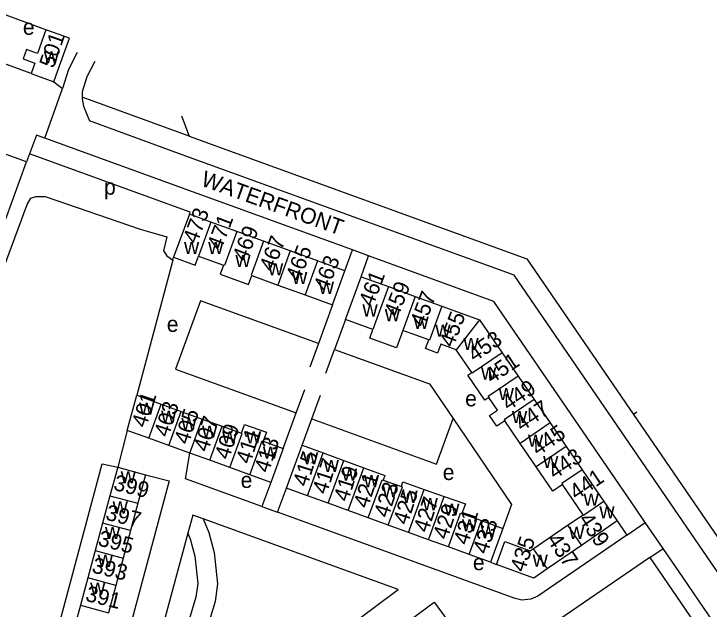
# Model space of a CAD drawing. Extents: x 154320 to 156262, y 382651 to 384180.
# Drawn here: x 155831.3 to 156007.7, y 383414.4 to 383565.5 of the extents above; entities that cross this region are included whole.
import ezdxf

# ---------------------------------------------------------------- set-up
doc = ezdxf.new("R2010")
doc.units = 0
for name, color, linetype in [('BLT_Basislijn', 7, 'Continuous'), ('BLT_Bebouwing', 7, 'Continuous'), ('BLT_Centroide', 7, 'Continuous'), ('BLT_Huisnummer', 7, 'Continuous'), ('BLT_Huisnummer_ tussenligend', 7, 'Continuous'), ('BLT_Onderverdeling_panden', 7, 'Continuous'), ('BLT_Straatnaam', 7, 'Continuous'), ('BLT_Vlakafsluiter', 7, 'Continuous')]:
    doc.layers.add(name, color=color, linetype=linetype)

msp = doc.modelspace()

# ---------------------------------------------------------------- linework, layer by layer
at = {"layer": 'BLT_Basislijn'}
for p, q in [((155839.44, 383561.42), (155828.37, 383565.46)), ((155835.65, 383550.35), (155824.35, 383554.45)), ((155847.33, 383555.63), (155845.19, 383551.33)), ((155851.81, 383553.41), (155849.84, 383549.45)), ((155845.19, 383551.33), (155843.65, 383546.5)), ((155841.45, 383548.21), (155843.65, 383546.5)), ((155875.74, 383534.42), (155848.6, 383544.29)), ((155835.3, 383529.97), (155834.5, 383527.86)), ((155876.04, 383515.15), (155835.3, 383529.97)), ((155875.83, 383514.59), (155876.04, 383515.15)), ((155915.27, 383500.24), (155917.18, 383505.52)), ((155871.64, 383502.96), (155871.84, 383503.71)), ((155919.39, 383498.74), (155921.3, 383504.02)), ((155871.64, 383502.96), (155862.48, 383468.66)), ((155912.14, 383491.6), (155908.57, 383481.75)), ((155915.42, 383487.85), (155912.67, 383480.28)), ((155908.57, 383481.75), (155906.4, 383475.76)), ((155902.91, 383464.14), (155905.09, 383470.09)), ((155906.89, 383462.69), (155909.06, 383468.64)), ((155899.62, 383455.13), (155902.91, 383464.14)), ((155904.43, 383455.95), (155906.89, 383462.69)), ((155988.48, 383463.76), (156062.92, 383355.09)), ((155860.08, 383459.73), (155857.69, 383450.39)), ((155894.23, 383440.37), (155898.21, 383438.92)), ((155876.67, 383438.23), (155875.44, 383433.65)), ((155879.36, 383437.25), (155876.67, 383438.23)), ((155928.8, 383419.3), (155879.36, 383437.25)), ((155984.38, 383436.72), (155986.84, 383433.14)), ((155986.84, 383433.14), (155991.5, 383436.34)), ((155996.02, 383429.74), (155991.5, 383436.34)), ((155875.44, 383433.65), (155863.47, 383389.12)), ((155992.7, 383427.46), (155996.02, 383429.74)), ((156001.19, 383422.21), (155996.02, 383429.74)), ((155952.21, 383426.27), (155953.78, 383425.69)), ((155880.52, 383383.56), (155928.8, 383419.3))]:
    msp.add_line(p, q, dxfattribs=at)
for points in [[(155849.84, 383549.45), (155848.63, 383545.66), (155848.6, 383544.29)], [(155848.6, 383544.29), (155848.59, 383543.89), (155848.93, 383542.06), (155850.47, 383538.29)], [(155874.03, 383529.72), (155850.47, 383538.29)], [(155839.17, 383533.88), (155837.06, 383534.63), (155835.3, 383529.97)], [(155877.81, 383519.83), (155839.17, 383533.88)], [(155875.74, 383534.42), (155961.42, 383503.27), (155988.48, 383463.76)], [(155834.5, 383527.86), (155828.41, 383530.07)], [(155984.36, 383460.93), (155958.2, 383499.12), (155874.03, 383529.72)], [(155802.41, 383439.57), (155834.5, 383527.86)], [(155917.18, 383505.52), (155877.81, 383519.83)], [(155801.1, 383435.95), (155802.24, 383435.39), (155804.95, 383437.68), (155805.97, 383439.73), (155834.64, 383517.07), (155835.62, 383518.64), (155836.89, 383519.06), (155839.22, 383519.08), (155863.38, 383510.83), (155865.12, 383510.28), (155870.15, 383508.84), (155869.25, 383505.27), (155870.15, 383504.05), (155871.64, 383502.96)], [(155921.3, 383504.02), (155917.18, 383505.52)], [(155991.5, 383436.34), (155989, 383439.99), (155953.05, 383492.48), (155921.3, 383504.02)], [(155908.57, 383481.75), (155878.62, 383492.61), (155872.32, 383475.28), (155902.91, 383464.14)], [(155910.49, 383474.29), (155912.67, 383480.28)], [(155912.67, 383480.28), (155936.73, 383471.52), (155942.75, 383462.7)], [(155906.89, 383462.69), (155938.55, 383451.17), (155942.75, 383462.7)], [(155942.75, 383462.7), (155957.59, 383440.92), (155955.36, 383434.85)], [(156059.13, 383351.78), (155984.36, 383460.93)], [(155894.23, 383440.37), (155874.86, 383447.4), (155875.95, 383453.97)], [(155893.74, 383356.42), (155867.19, 383336.88), (155863.3, 383342.14), (155860.43, 383340.02), (155833.63, 383376.29), (155853.7, 383451.27), (155857.69, 383450.39)], [(155864.7, 383448.43), (155870.72, 383446.91), (155852.73, 383380), (155865.63, 383362.58)], [(155896.46, 383446.52), (155894.23, 383440.37)], [(155898.21, 383438.92), (155900.44, 383445.06)], [(155986.84, 383433.14), (155964.26, 383417.67), (155962.49, 383416.86), (155960.21, 383416.66), (155958.48, 383417.03), (155898.21, 383438.92)], [(155879.36, 383437.25), (155880.77, 383433.8), (155882.14, 383428.69), (155883, 383420.76), (155882.37, 383416.32), (155880.32, 383409.6), (155878.81, 383403.15), (155878.46, 383396.68), (155879.53, 383387.88), (155880.52, 383383.56)], [(155875.44, 383433.65), (155876.02, 383432.2), (155877.22, 383427.77), (155877.96, 383420.85), (155877.47, 383417.41), (155875.49, 383410.9), (155873.84, 383403.86), (155873.44, 383396.51), (155874.6, 383387.02), (155876.14, 383380.31)], [(155992.7, 383427.46), (156010.8, 383400.93), (155937.34, 383331.15)], [(155992.7, 383427.46), (155968.2, 383410.67), (155964.55, 383409.02), (155964.22, 383408.99)], [(156012.64, 383405.48), (156001.19, 383422.21)], [(155883.47, 383375.78), (155937.95, 383416.11), (155942.37, 383410.13)]]:
    msp.add_lwpolyline(points, dxfattribs=at)
at = {"layer": 'BLT_Bebouwing'}
for p, q in [((155839.44, 383561.42), (155837.3, 383555.44)), ((155845.45, 383559.26), (155839.44, 383561.42)), ((155842.49, 383551.06), (155845.45, 383559.26)), ((155834.53, 383556.45), (155833.65, 383554.05)), ((155837.3, 383555.44), (155834.53, 383556.45)), ((155833.65, 383554.05), (155836.6, 383552.98)), ((155836.6, 383552.98), (155835.65, 383550.35)), ((155841.45, 383548.21), (155842.49, 383551.06)), ((155835.65, 383550.35), (155841.45, 383548.21)), ((155887.88, 383510.21), (155881.3, 383512.6)), ((155894.64, 383507.75), (155887.88, 383510.21)), ((155901.41, 383505.29), (155894.64, 383507.75)), ((155908.34, 383502.77), (155901.41, 383505.29)), ((155878.14, 383503.97), (155884.48, 383501.64)), ((155915.27, 383500.24), (155908.34, 383502.77)), ((155912.14, 383491.6), (155915.27, 383500.24)), ((155891.69, 383499.01), (155898.24, 383496.63)), ((155915.42, 383487.85), (155919.39, 383498.74)), ((155919.39, 383498.74), (155926.34, 383496.22)), ((155898.24, 383496.63), (155905.19, 383494.12)), ((155926.34, 383496.22), (155933.14, 383493.74)), ((155905.19, 383494.12), (155912.14, 383491.6)), ((155933.14, 383493.74), (155939.91, 383491.28)), ((155939.91, 383491.28), (155949.46, 383487.81)), ((155922.38, 383485.32), (155915.42, 383487.85)), ((155949.46, 383487.81), (155955.2, 383479.41)), ((155936.55, 383482.73), (155930, 383485.1)), ((155947.46, 383474.43), (155943.54, 383480.18)), ((155955.2, 383479.41), (155959.24, 383473.5)), ((155959.24, 383473.5), (155963.3, 383467.56)), ((155860.08, 383459.73), (155862.48, 383468.66)), ((155862.48, 383468.66), (155868.7, 383466.39)), ((155868.7, 383466.39), (155873.78, 383464.54)), ((155963.3, 383467.56), (155967.36, 383461.62)), ((155873.78, 383464.54), (155879.08, 383462.61)), ((155879.08, 383462.61), (155884.15, 383460.76)), ((155967.36, 383461.62), (155971.43, 383455.67)), ((155865.53, 383457.75), (155860.08, 383459.73)), ((155884.15, 383460.76), (155889.02, 383458.99)), ((155870.63, 383455.9), (155865.53, 383457.75)), ((155875.95, 383453.97), (155870.63, 383455.9)), ((155894.54, 383456.99), (155899.62, 383455.13)), ((155900.44, 383445.06), (155904.43, 383455.95)), ((155904.43, 383455.95), (155909.77, 383453.99)), ((155963.81, 383450.47), (155959.76, 383456.41)), ((155971.43, 383455.67), (155975.49, 383449.73)), ((155881.02, 383452.13), (155875.95, 383453.97)), ((155899.62, 383455.13), (155896.46, 383446.52)), ((155909.77, 383453.99), (155914.98, 383452.08)), ((155886.08, 383450.29), (155881.02, 383452.13)), ((155857.69, 383450.39), (155855.64, 383443.13)), ((155857.69, 383450.39), (155864.7, 383448.43)), ((155914.98, 383452.08), (155920.07, 383450.21)), ((155891.2, 383448.43), (155886.08, 383450.29)), ((155975.49, 383449.73), (155981.02, 383441.63)), ((155896.46, 383446.52), (155891.2, 383448.43)), ((155924.99, 383447.12), (155929.63, 383445.5)), ((155905.82, 383443.1), (155900.44, 383445.06)), ((155975.72, 383438.32), (155970.49, 383446)), ((155935.39, 383444.75), (155940.46, 383442.98)), ((155855.64, 383443.13), (155853.77, 383436.18)), ((155911.05, 383441.21), (155905.82, 383443.1)), ((155862.77, 383441.22), (155860.91, 383434.27)), ((155916.13, 383439.36), (155911.05, 383441.21)), ((155921.23, 383437.51), (155916.13, 383439.36)), ((155944.95, 383438.64), (155949.91, 383436.84)), ((155971.79, 383435.63), (155975.72, 383438.32)), ((155926.31, 383435.67), (155921.23, 383437.51)), ((155949.91, 383436.84), (155955.36, 383434.85)), ((155853.77, 383436.18), (155851.91, 383429.22)), ((155931.39, 383433.82), (155926.31, 383435.67)), ((155955.36, 383434.85), (155952.21, 383426.27)), ((155963.1, 383429.69), (155971.79, 383435.63)), ((155860.91, 383434.27), (155859.05, 383427.31)), ((155936.47, 383431.98), (155931.39, 383433.82)), ((155941.54, 383430.14), (155936.47, 383431.98)), ((155851.91, 383429.22), (155850.05, 383422.27)), ((155946.79, 383428.24), (155941.54, 383430.14)), ((155975.3, 383430.51), (155966.61, 383424.57)), ((155952.21, 383426.27), (155946.79, 383428.24)), ((155859.05, 383427.31), (155857.19, 383420.36)), ((155850.05, 383422.27), (155848.18, 383415.32)), ((155857.19, 383420.36), (155855.33, 383413.4)), ((155848.18, 383415.32), (155846.32, 383408.35))]:
    msp.add_line(p, q, dxfattribs=at)
for points in [[(155875.83, 383514.59), (155871.84, 383503.71)], [(155881.3, 383512.6), (155875.83, 383514.59)], [(155871.84, 383503.71), (155877.31, 383501.71), (155878.14, 383503.97)], [(155884.48, 383501.64), (155883.65, 383499.38), (155890.85, 383496.74), (155891.69, 383499.01)], [(155930, 383485.1), (155928.37, 383480.65), (155921.63, 383483.11), (155922.38, 383485.32)], [(155943.54, 383480.18), (155939.62, 383481.62), (155938.8, 383479.35), (155935.73, 383480.47), (155936.55, 383482.73)], [(155951.81, 383468.1), (155950.79, 383467.4), (155946.48, 383473.76), (155947.46, 383474.43)], [(155955.85, 383462.15), (155953.87, 383460.8), (155952.01, 383463.5), (155954.01, 383464.85), (155951.81, 383468.1)], [(155889.02, 383458.99), (155889.85, 383461.25), (155895.36, 383459.25), (155894.54, 383456.99)], [(155959.76, 383456.41), (155955.85, 383462.15)], [(155970.49, 383446), (155968.01, 383444.31), (155963.81, 383450.47)], [(155920.07, 383450.21), (155925.39, 383448.26), (155924.99, 383447.12)], [(155864.7, 383448.43), (155862.77, 383441.22)], [(155929.63, 383445.5), (155930.03, 383446.63), (155935.39, 383444.75)], [(155940.46, 383442.98), (155945.85, 383441.09), (155944.95, 383438.64)], [(155981.02, 383441.63), (155984.38, 383436.72)], [(155984.38, 383436.72), (155975.3, 383430.51)], [(155953.78, 383425.69), (155955.84, 383431.48), (155962.29, 383429.14), (155963.1, 383429.69)], [(155963.2, 383422.24), (155953.78, 383425.69)], [(155966.61, 383424.57), (155963.2, 383422.24)]]:
    msp.add_lwpolyline(points, dxfattribs=at)
at = {"layer": 'BLT_Onderverdeling_panden'}
for p, q in [((155881.3, 383512.6), (155878.14, 383503.97)), ((155887.88, 383510.21), (155884.71, 383501.56)), ((155894.64, 383507.75), (155891.48, 383499.09)), ((155901.41, 383505.29), (155898.24, 383496.63)), ((155884.71, 383501.56), (155884.48, 383501.64)), ((155908.34, 383502.77), (155905.19, 383494.12)), ((155891.48, 383499.09), (155891.69, 383499.01)), ((155926.34, 383496.22), (155922.38, 383485.32)), ((155933.14, 383493.74), (155930, 383485.1)), ((155939.91, 383491.28), (155936.77, 383482.65)), ((155949.46, 383487.81), (155943.54, 383480.18)), ((155936.77, 383482.65), (155936.55, 383482.73)), ((155955.2, 383479.41), (155947.6, 383474.23)), ((155947.6, 383474.23), (155947.46, 383474.43)), ((155959.24, 383473.5), (155951.65, 383468.33)), ((155951.65, 383468.33), (155951.81, 383468.1)), ((155865.53, 383457.75), (155868.7, 383466.39)), ((155870.63, 383455.9), (155873.78, 383464.54)), ((155875.95, 383453.97), (155879.08, 383462.61)), ((155967.36, 383461.62), (155959.76, 383456.41)), ((155881.02, 383452.13), (155884.15, 383460.76)), ((155971.43, 383455.67), (155963.81, 383450.47)), ((155905.82, 383443.1), (155909.77, 383453.99)), ((155911.05, 383441.21), (155914.98, 383452.08)), ((155916.13, 383439.36), (155920.07, 383450.21)), ((155931.39, 383433.82), (155935.39, 383444.75)), ((155855.64, 383443.13), (155862.77, 383441.22)), ((155936.47, 383431.98), (155940.46, 383442.98)), ((155946.79, 383428.24), (155949.91, 383436.84)), ((155860.91, 383434.27), (155853.77, 383436.18)), ((155971.79, 383435.63), (155975.3, 383430.51)), ((155851.91, 383429.22), (155859.05, 383427.31)), ((155963.1, 383429.69), (155966.61, 383424.57)), ((155857.19, 383420.36), (155850.05, 383422.27)), ((155848.18, 383415.32), (155855.33, 383413.4))]:
    msp.add_line(p, q, dxfattribs=at)
for points in [[(155963.3, 383467.56), (155955.7, 383462.37), (155955.85, 383462.15)], [(155886.08, 383450.29), (155889.22, 383458.92), (155889.02, 383458.99)], [(155891.2, 383448.43), (155894.33, 383457.06), (155894.54, 383456.99)], [(155975.49, 383449.73), (155970.35, 383446.21), (155970.49, 383446)], [(155921.23, 383437.51), (155924.77, 383447.2), (155924.99, 383447.12)], [(155926.31, 383435.67), (155929.87, 383445.41), (155929.63, 383445.5)], [(155981.02, 383441.63), (155975.86, 383438.11), (155975.72, 383438.32)], [(155941.54, 383430.14), (155944.66, 383438.74), (155944.95, 383438.64)]]:
    msp.add_lwpolyline(points, dxfattribs=at)
at = {"layer": 'BLT_Vlakafsluiter'}
for p, q in [((155839.17, 383533.88), (155843.65, 383546.5)), ((155873.86, 383539.56), (155875.74, 383534.42)), ((155989.35, 383464.35), (155988.48, 383463.76))]:
    msp.add_line(p, q, dxfattribs=at)

# ---------------------------------------------------------------- texts
at = {"layer": 'BLT_Centroide'}
for s, p in [('e', (155833.58, 383560.15)), ('w', (155838.9, 383552.89)), ('p', (155854.17, 383519.55)), ('w', (155874.46, 383504.51)), ('w', (155880.59, 383504.48)), ('w', (155887.5, 383501.21)), ('w', (155895.77, 383499.08)), ('w', (155901.88, 383496.85)), ('w', (155908.66, 383494.38)), ('w', (155919.75, 383488.63)), ('w', (155925.42, 383487.43)), ('e', (155870.1, 383484.74)), ('w', (155932.69, 383485.5)), ('w', (155938.23, 383483.48)), ('w', (155945.37, 383480.13)), ('w', (155949.84, 383472.62)), ('w', (155954.31, 383467.41)), ('e', (155945.8, 383465.83)), ('w', (155863.07, 383463.69)), ('w', (155868.66, 383461.65)), ('w', (155957.68, 383461.57)), ('w', (155873.79, 383459.78)), ('w', (155879.03, 383457.87)), ('w', (155884.13, 383456.4)), ('w', (155890.2, 383456.4)), ('w', (155961.75, 383455.57)), ('w', (155894.47, 383452.53)), ('w', (155904.66, 383451.07)), ('w', (155909.91, 383449.16)), ('w', (155965.58, 383450.16)), ('w', (155858.38, 383446.29)), ('w', (155914.52, 383446.93)), ('e', (155940.12, 383447.12)), ('e', (155888.84, 383445.11)), ('w', (155920.09, 383445.29)), ('w', (155924.79, 383442.69)), ('w', (155929.87, 383441.32)), ('w', (155975.85, 383440.59)), ('w', (155856.35, 383438.62)), ('w', (155935, 383439.45)), ('w', (155940.5, 383438.09)), ('w', (155979.86, 383437.39)), ('w', (155944.98, 383434.09)), ('w', (155854.41, 383432.11)), ('w', (155949.77, 383432.35)), ('w', (155972.15, 383432.18)), ('w', (155852.58, 383425.07)), ('w', (155962.93, 383425.14)), ('e', (155947.77, 383424.23)), ('w', (155850.64, 383418.03))]:
    msp.add_text(s, height=4, dxfattribs=at).set_placement(p)
at = {"layer": 'BLT_Huisnummer'}
for s, rotation, p in [('501', 71.0029, (155841.39, 383551.47)), ('473', 69.0883, (155877.73, 383506.89)), ('467', 69.0883, (155897.13, 383499.78)), ('463', 69.0883, (155910.89, 383494.8)), ('461', 69.0883, (155922.38, 383490.93)), ('457', 69.0883, (155935.38, 383485.71)), ('453', 34.0883, (155948.17, 383476.95)), ('449', 34.0883, (155956.77, 383464.54)), ('401', 72.0883, (155864.82, 383460.19)), ('405', 72.0883, (155875.61, 383455.91)), ('409', 72.0883, (155885.89, 383452.09)), ('445', 34.0883, (155964.27, 383453.12)), ('413', 72.0883, (155895.95, 383448.74)), ('415', 72.0883, (155905.72, 383445.2)), ('419', 72.0883, (155916.07, 383441.39)), ('441', 34.0883, (155973.99, 383441.91)), ('399', 346.0883, (155856.36, 383444.66)), ('423', 72.0883, (155926.29, 383437.32)), ('427', 72.0883, (155936.36, 383433.55)), ('433', 72.0883, (155951.4, 383428.08)), ('439', 304.0883, (155974.41, 383437.13)), ('395', 346.0883, (155852.41, 383430.54)), ('435', 72.0883, (155960.89, 383423.52)), ('391', 346.0883, (155849.24, 383416.49))]:
    msp.add_text(s, height=4, rotation=rotation, dxfattribs=at).set_placement(p)
at = {"layer": 'BLT_Huisnummer_ tussenligend'}
for s, rotation, p in [('471', 69.0883, (155883.88, 383505.24)), ('469', 69.0883, (155890.3, 383502.34)), ('465', 69.0883, (155903.84, 383497.38)), ('459', 69.0883, (155928.79, 383488.22)), ('455', 69.0883, (155942.79, 383480.57)), ('451', 34.0883, (155952.54, 383471.39)), ('403', 72.0883, (155870.51, 383457.78)), ('447', 34.0883, (155960.17, 383459.31)), ('407', 72.0883, (155880.52, 383454.04)), ('411', 72.0883, (155891.26, 383450.98)), ('443', 34.0883, (155968.52, 383447.15)), ('417', 72.0883, (155910.67, 383443.28)), ('421', 72.0883, (155921.12, 383439.74)), ('425', 72.0883, (155931.17, 383435.52)), ('397', 346.0883, (155854.34, 383437.1)), ('429', 72.0883, (155941.29, 383431.8)), ('431', 72.0883, (155946.47, 383430.41)), ('437', 304.0883, (155966.41, 383431.93)), ('393', 346.0883, (155850.87, 383423.7))]:
    msp.add_text(s, height=4, rotation=rotation, dxfattribs=at).set_placement(p)
at = {"layer": 'BLT_Straatnaam'}
msp.add_text('WATERFRONT', height=4, rotation=340.2347, dxfattribs=at).set_placement((155878.52, 383521.96))

doc.saveas('drawing.dxf')
